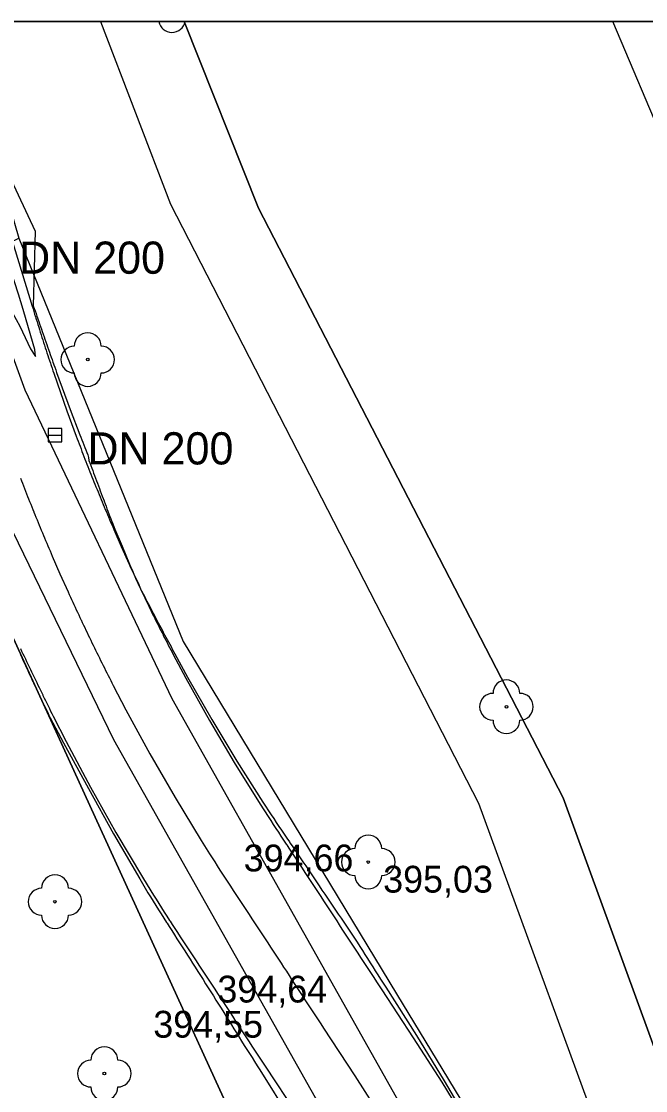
# Model space of a CAD drawing. Extents: x -574342 to -508101, y -1143544 to -1123894.
# Drawn here: x -508473.95 to -508450.68, y -1143155.94 to -1143116.06 of the extents above; entities that cross this region are included whole.
import ezdxf

# ---------------------------------------------------------------- set-up
doc = ezdxf.new("R2010")
doc.units = 0
for name, color, linetype in [('01_PARCELY_NAVRH_PC', 7, 'Continuous'), ('01_PARCELY_NAVRH_ŽP', 7, 'Continuous'), ('1000', 7, 'Continuous'), ('15', 7, 'Continuous'), ('21', 7, 'Continuous'), ('37', 7, 'Continuous'), ('52', 7, 'Continuous'), ('54', 7, 'Continuous'), ('55', 7, 'Continuous'), ('Level 1', 7, 'Continuous'), ('Level 255', 7, 'Continuous'), ('VRST VEDL', 7, 'Continuous')]:
    doc.layers.add(name, color=color, linetype=linetype)

msp = doc.modelspace()

# ---------------------------------------------------------------- linework, layer by layer
at = {"layer": '01_PARCELY_NAVRH_PC'}
msp.add_lwpolyline([(-508445.99, -1143206.42), (-508454.33, -1143183.49), (-508456.87, -1143173.84), (-508463.3, -1143163.03), (-508476.26, -1143134.7), (-508479.46, -1143126.74), (-508474.05, -1143124.14), (-508467.92, -1143139.18), (-508459.97, -1143152.33), (-508456.09, -1143158.71), (-508451.57, -1143168.14), (-508437.66, -1143207.58)], dxfattribs=at)
at = {"layer": '01_PARCELY_NAVRH_ŽP'}
for p, q in [((-508467.879, -1143116.058), (-508476.398, -1143116.058)), ((-508437, -1143116.058), (-508467.879, -1143116.058))]:
    msp.add_line(p, q, dxfattribs=at)
for points in [[(-508476.398, -1143116.058), (-508474.05, -1143124.14), (-508467.92, -1143139.18), (-508459.97, -1143152.33), (-508456.09, -1143158.71), (-508451.57, -1143168.14), (-508437.66, -1143207.58), (-508425.52, -1143241.92), (-508422.7, -1143249.88), (-508420.04, -1143252.1), (-508417.38, -1143252.95), (-508415.56, -1143252.78), (-508448.24, -1143160.16), (-508453.75, -1143145.01), (-508465.11, -1143123.03), (-508467.879, -1143116.058)], [(-508467.879, -1143116.058), (-508465.11, -1143123.03), (-508453.75, -1143145.01), (-508448.24, -1143160.16), (-508415.56, -1143252.78), (-508437, -1143116.058)]]:
    msp.add_lwpolyline(points, dxfattribs=at)
msp.add_lwpolyline([(-508521.06, -1143176.58), (-508518.2, -1143171.1), (-508515.68, -1143172.08), (-508512.27, -1143171.56), (-508509.12, -1143169.33), (-508497.89, -1143158.09), (-508486.83, -1143153.3), (-508481.34, -1143149.03), (-508479.12, -1143143.52), (-508479.68, -1143136.88), (-508476.26, -1143134.7), (-508463.3, -1143163.03), (-508471.45, -1143157.79), (-508480.5, -1143156.13), (-508491.25, -1143159.19), (-508499.36, -1143164.43), (-508507.52, -1143173.92), (-508509.38, -1143179.27), (-508513.26, -1143177.6)], close=True, dxfattribs=at)
at = {"layer": '1000'}
for points in [[(-508476.731, -1143116.058), (-508476.722, -1143116.092), (-508476.694, -1143116.192), (-508476.667, -1143116.292), (-508476.64, -1143116.392), (-508476.613, -1143116.492), (-508476.585, -1143116.592), (-508476.558, -1143116.691), (-508476.53, -1143116.791), (-508476.502, -1143116.891), (-508476.475, -1143116.991), (-508476.447, -1143117.091), (-508476.419, -1143117.19), (-508476.391, -1143117.29), (-508476.362, -1143117.39), (-508476.334, -1143117.489), (-508476.306, -1143117.589), (-508476.277, -1143117.689), (-508476.249, -1143117.788), (-508476.22, -1143117.888), (-508476.192, -1143117.987), (-508476.163, -1143118.087), (-508473.44, -1143123.887)], [(-508473.44, -1143123.887), (-508473.509, -1143126.661), (-508473.475, -1143126.76), (-508473.441, -1143126.858), (-508473.407, -1143126.956), (-508473.373, -1143127.055), (-508473.354, -1143127.11), (-508473.339, -1143127.152), (-508473.306, -1143127.247), (-508473.273, -1143127.342), (-508473.24, -1143127.437), (-508473.207, -1143127.532), (-508473.174, -1143127.628), (-508473.141, -1143127.723), (-508473.108, -1143127.818), (-508473.075, -1143127.913), (-508473.042, -1143128.008), (-508473.009, -1143128.103), (-508472.976, -1143128.198), (-508472.943, -1143128.293), (-508472.909, -1143128.389), (-508472.876, -1143128.484), (-508472.842, -1143128.578), (-508472.808, -1143128.673), (-508472.774, -1143128.768), (-508472.753, -1143128.827), (-508472.74, -1143128.863), (-508472.706, -1143128.958), (-508472.672, -1143129.052), (-508472.638, -1143129.147), (-508472.129, -1143130.534), (-508471.77, -1143131.474), (-508471.733, -1143131.569), (-508471.696, -1143131.663), (-508471.659, -1143131.757), (-508471.622, -1143131.852), (-508471.585, -1143131.946), (-508471.547, -1143132.04), (-508471.509, -1143132.134), (-508471.473, -1143132.227), (-508471.472, -1143132.228), (-508471.445, -1143132.326), (-508471.432, -1143132.429), (-508471.399, -1143132.525), (-508471.364, -1143132.621), (-508471.329, -1143132.716), (-508471.294, -1143132.811), (-508471.258, -1143132.906), (-508471.222, -1143133), (-508471.186, -1143133.095), (-508471.15, -1143133.19), (-508471.115, -1143133.285), (-508471.08, -1143133.379), (-508471.08, -1143133.38), (-508471.045, -1143133.475), (-508471.01, -1143133.571), (-508470.975, -1143133.666), (-508470.94, -1143133.761), (-508470.905, -1143133.856), (-508470.872, -1143133.944), (-508470.869, -1143133.951), (-508470.834, -1143134.046), (-508470.798, -1143134.141), (-508470.761, -1143134.235), (-508470.725, -1143134.33), (-508470.688, -1143134.425), (-508470.651, -1143134.519), (-508470.614, -1143134.613), (-508470.577, -1143134.708), (-508470.539, -1143134.802), (-508470.502, -1143134.896), (-508470.464, -1143134.99), (-508470.199, -1143135.634), (-508469.92, -1143136.297), (-508469.88, -1143136.391), (-508469.841, -1143136.484), (-508469.801, -1143136.577), (-508469.761, -1143136.671), (-508469.721, -1143136.764), (-508469.598, -1143136.998), (-508469.508, -1143137.224), (-508469.469, -1143137.301), (-508469.462, -1143137.314), (-508469.415, -1143137.404), (-508469.369, -1143137.495), (-508469.322, -1143137.585), (-508469.275, -1143137.675), (-508469.228, -1143137.765), (-508469.182, -1143137.855), (-508469.135, -1143137.945), (-508469.088, -1143138.035), (-508469.041, -1143138.125), (-508468.995, -1143138.215), (-508468.948, -1143138.305), (-508468.901, -1143138.394), (-508468.901, -1143138.395), (-508468.853, -1143138.484), (-508468.805, -1143138.573), (-508468.758, -1143138.663), (-508468.71, -1143138.752), (-508468.662, -1143138.842), (-508468.624, -1143138.913), (-508468.614, -1143138.931), (-508468.566, -1143139.02), (-508468.518, -1143139.11), (-508468.47, -1143139.199), (-508468.422, -1143139.288), (-508468.374, -1143139.378), (-508468.326, -1143139.467), (-508468.278, -1143139.556), (-508468.23, -1143139.645), (-508467.757, -1143140.512), (-508466.856, -1143142.09), (-508465.92, -1143143.646), (-508464.948, -1143145.18), (-508464.643, -1143145.647), (-508464.547, -1143145.792), (-508464.45, -1143145.937), (-508464.353, -1143146.082), (-508464.255, -1143146.227), (-508464.157, -1143146.371), (-508464.059, -1143146.516), (-508463.96, -1143146.66), (-508463.94, -1143146.689), (-508463.94, -1143146.689), (-508463.86, -1143146.808), (-508463.759, -1143146.958), (-508463.658, -1143147.108), (-508463.556, -1143147.257), (-508463.455, -1143147.407), (-508463.354, -1143147.556), (-508463.252, -1143147.706), (-508463.151, -1143147.855), (-508463.049, -1143148.005), (-508462.948, -1143148.154), (-508462.847, -1143148.304), (-508462.746, -1143148.454), (-508462.645, -1143148.603), (-508462.543, -1143148.753), (-508462.442, -1143148.902), (-508462.34, -1143149.052), (-508462.239, -1143149.201), (-508462.137, -1143149.35), (-508462.035, -1143149.5), (-508461.933, -1143149.649), (-508461.834, -1143149.8), (-508461.734, -1143149.951), (-508461.635, -1143150.101), (-508461.536, -1143150.252), (-508461.436, -1143150.403), (-508461.339, -1143150.555), (-508461.242, -1143150.708), (-508461.146, -1143150.861), (-508461.049, -1143151.013), (-508460.952, -1143151.166), (-508460.855, -1143151.318), (-508460.758, -1143151.47), (-508460.661, -1143151.623), (-508460.564, -1143151.775), (-508460.467, -1143151.928), (-508460.371, -1143152.08), (-508459.228, -1143153.886), (-508458.193, -1143155.565), (-508457.198, -1143157.266)], [(-508474.325, -1143124.158), (-508473.55, -1143126.674), (-508473.519, -1143126.773), (-508473.488, -1143126.873), (-508473.458, -1143126.972), (-508473.427, -1143127.071), (-508473.41, -1143127.128), (-508473.397, -1143127.169), (-508473.367, -1143127.266), (-508473.337, -1143127.362), (-508473.307, -1143127.458), (-508473.277, -1143127.554), (-508473.247, -1143127.651), (-508473.216, -1143127.747), (-508473.186, -1143127.843), (-508473.155, -1143127.939), (-508473.124, -1143128.035), (-508473.093, -1143128.131), (-508473.062, -1143128.227), (-508473.031, -1143128.322), (-508473, -1143128.418), (-508472.968, -1143128.514), (-508472.937, -1143128.61), (-508472.905, -1143128.705), (-508472.873, -1143128.801), (-508472.854, -1143128.86), (-508472.842, -1143128.897), (-508472.81, -1143128.992), (-508472.777, -1143129.088), (-508472.745, -1143129.183), (-508472.257, -1143130.58), (-508471.909, -1143131.527), (-508471.873, -1143131.622), (-508471.837, -1143131.717), (-508471.801, -1143131.811), (-508471.765, -1143131.906), (-508471.729, -1143132.001), (-508471.693, -1143132.096), (-508471.656, -1143132.19), (-508471.62, -1143132.284), (-508471.62, -1143132.285), (-508471.583, -1143132.38), (-508471.546, -1143132.474), (-508471.509, -1143132.569), (-508471.472, -1143132.663), (-508471.435, -1143132.758), (-508471.398, -1143132.852), (-508471.361, -1143132.946), (-508471.323, -1143133.041), (-508471.285, -1143133.135), (-508471.247, -1143133.229), (-508471.21, -1143133.323), (-508471.172, -1143133.416), (-508471.172, -1143133.417), (-508471.133, -1143133.511), (-508471.095, -1143133.605), (-508471.057, -1143133.699), (-508471.018, -1143133.793), (-508470.979, -1143133.887), (-508470.943, -1143133.974), (-508470.941, -1143133.98), (-508470.902, -1143134.074), (-508470.863, -1143134.168), (-508470.824, -1143134.261), (-508470.784, -1143134.355), (-508470.745, -1143134.449), (-508470.705, -1143134.542), (-508470.666, -1143134.635), (-508470.626, -1143134.729), (-508470.586, -1143134.822), (-508470.546, -1143134.915), (-508470.506, -1143135.008), (-508470.227, -1143135.647), (-508469.933, -1143136.303), (-508469.891, -1143136.396), (-508469.849, -1143136.488), (-508469.807, -1143136.58), (-508469.765, -1143136.672), (-508469.723, -1143136.765), (-508469.68, -1143136.857), (-508469.637, -1143136.949), (-508469.595, -1143137.041), (-508469.552, -1143137.133), (-508469.509, -1143137.224), (-508469.472, -1143137.303), (-508469.466, -1143137.316), (-508469.422, -1143137.408), (-508469.379, -1143137.5), (-508469.335, -1143137.591), (-508469.292, -1143137.683), (-508469.248, -1143137.774), (-508469.204, -1143137.866), (-508469.16, -1143137.957), (-508469.116, -1143138.048), (-508469.072, -1143138.14), (-508469.028, -1143138.231), (-508468.983, -1143138.322), (-508468.939, -1143138.412), (-508468.939, -1143138.413), (-508468.893, -1143138.504), (-508468.847, -1143138.594), (-508468.802, -1143138.685), (-508468.756, -1143138.775), (-508468.709, -1143138.865), (-508468.673, -1143138.937), (-508468.663, -1143138.956), (-508468.617, -1143139.046), (-508468.57, -1143139.136), (-508468.524, -1143139.226), (-508468.477, -1143139.316), (-508468.43, -1143139.406), (-508468.384, -1143139.496), (-508468.337, -1143139.586), (-508468.289, -1143139.676), (-508467.824, -1143140.547), (-508466.938, -1143142.136), (-508466.015, -1143143.703), (-508465.056, -1143145.247), (-508464.754, -1143145.717), (-508464.659, -1143145.864), (-508464.563, -1143146.01), (-508464.468, -1143146.156), (-508464.371, -1143146.302), (-508464.275, -1143146.448), (-508464.178, -1143146.593), (-508464.081, -1143146.739), (-508464.061, -1143146.768), (-508464.061, -1143146.769), (-508463.982, -1143146.888), (-508463.883, -1143147.039), (-508463.784, -1143147.191), (-508463.685, -1143147.342), (-508463.586, -1143147.493), (-508463.487, -1143147.644), (-508463.388, -1143147.795), (-508463.289, -1143147.946), (-508463.19, -1143148.097), (-508463.09, -1143148.248), (-508462.991, -1143148.399), (-508462.892, -1143148.55), (-508462.793, -1143148.701), (-508462.694, -1143148.852), (-508462.595, -1143149.003), (-508462.496, -1143149.154), (-508462.397, -1143149.305), (-508462.298, -1143149.456), (-508462.199, -1143149.607), (-508462.1, -1143149.758), (-508462.001, -1143149.909), (-508461.901, -1143150.06), (-508461.802, -1143150.211), (-508461.703, -1143150.362), (-508461.604, -1143150.513), (-508461.505, -1143150.664), (-508461.406, -1143150.815), (-508461.307, -1143150.966), (-508461.208, -1143151.117), (-508461.109, -1143151.268), (-508461.01, -1143151.419), (-508460.911, -1143151.57), (-508460.812, -1143151.722), (-508460.712, -1143151.873), (-508460.613, -1143152.024), (-508460.514, -1143152.175), (-508459.342, -1143153.961), (-508458.282, -1143155.62), (-508457.262, -1143157.304)], [(-508473.99, -1143139.445), (-508473.944, -1143139.543), (-508473.897, -1143139.641), (-508473.851, -1143139.738), (-508473.805, -1143139.836), (-508473.758, -1143139.933), (-508473.711, -1143140.03), (-508473.665, -1143140.128), (-508473.618, -1143140.225), (-508473.571, -1143140.322), (-508473.523, -1143140.419), (-508473.476, -1143140.516), (-508473.429, -1143140.612), (-508473.429, -1143140.613), (-508473.382, -1143140.71), (-508473.335, -1143140.808), (-508473.288, -1143140.905), (-508473.241, -1143141.002), (-508473.194, -1143141.099), (-508473.157, -1143141.177), (-508473.147, -1143141.196), (-508473.1, -1143141.293), (-508473.052, -1143141.39), (-508473.005, -1143141.487), (-508472.957, -1143141.584), (-508472.909, -1143141.681), (-508472.861, -1143141.778), (-508472.813, -1143141.874), (-508472.764, -1143141.971), (-508472.287, -1143142.909), (-508471.377, -1143144.62), (-508470.427, -1143146.31), (-508469.437, -1143147.977), (-508469.126, -1143148.484), (-508469.027, -1143148.643), (-508468.929, -1143148.801), (-508468.83, -1143148.959), (-508468.73, -1143149.117), (-508468.63, -1143149.274), (-508468.53, -1143149.431), (-508468.43, -1143149.589), (-508468.409, -1143149.621), (-508468.409, -1143149.621), (-508468.33, -1143149.741), (-508468.231, -1143149.892), (-508468.132, -1143150.043), (-508468.033, -1143150.194), (-508467.934, -1143150.345), (-508467.835, -1143150.496), (-508467.736, -1143150.647), (-508467.637, -1143150.798), (-508467.537, -1143150.949), (-508467.438, -1143151.1), (-508467.339, -1143151.251), (-508467.24, -1143151.402), (-508467.141, -1143151.553), (-508467.042, -1143151.704), (-508466.943, -1143151.855), (-508466.844, -1143152.006), (-508466.745, -1143152.157), (-508466.646, -1143152.308), (-508466.547, -1143152.459), (-508466.448, -1143152.61), (-508466.348, -1143152.761), (-508466.249, -1143152.913), (-508466.15, -1143153.064), (-508466.051, -1143153.215), (-508465.952, -1143153.366), (-508465.853, -1143153.517), (-508465.754, -1143153.668), (-508465.655, -1143153.819), (-508465.556, -1143153.97), (-508465.457, -1143154.121), (-508465.358, -1143154.272), (-508465.259, -1143154.423), (-508465.159, -1143154.574), (-508465.06, -1143154.725), (-508464.961, -1143154.876), (-508464.862, -1143155.027), (-508463.69, -1143156.813)], [(-508473.985, -1143139.682), (-508473.94, -1143139.78), (-508473.894, -1143139.878), (-508473.849, -1143139.976), (-508473.804, -1143140.075), (-508473.759, -1143140.173), (-508473.714, -1143140.272), (-508473.669, -1143140.37), (-508473.623, -1143140.468), (-508473.577, -1143140.566), (-508473.532, -1143140.663), (-508473.531, -1143140.663), (-508473.486, -1143140.762), (-508473.44, -1143140.86), (-508473.395, -1143140.958), (-508473.349, -1143141.055), (-508473.302, -1143141.153), (-508473.265, -1143141.231), (-508473.256, -1143141.251), (-508473.209, -1143141.348), (-508473.162, -1143141.446), (-508473.115, -1143141.543), (-508473.067, -1143141.64), (-508473.02, -1143141.737), (-508472.972, -1143141.834), (-508472.924, -1143141.931), (-508472.875, -1143142.028), (-508472.385, -1143142.961), (-508471.455, -1143144.663), (-508470.519, -1143146.364), (-508469.543, -1143148.043), (-508469.235, -1143148.553), (-508469.137, -1143148.712), (-508469.039, -1143148.871), (-508468.94, -1143149.03), (-508468.841, -1143149.188), (-508468.742, -1143149.347), (-508468.643, -1143149.505), (-508468.543, -1143149.663), (-508468.523, -1143149.695), (-508468.522, -1143149.696), (-508468.445, -1143149.816), (-508468.347, -1143149.968), (-508468.249, -1143150.12), (-508468.152, -1143150.272), (-508468.054, -1143150.424), (-508467.957, -1143150.576), (-508467.859, -1143150.728), (-508467.762, -1143150.88), (-508467.665, -1143151.033), (-508467.568, -1143151.185), (-508467.471, -1143151.337), (-508467.374, -1143151.49), (-508467.277, -1143151.642), (-508467.18, -1143151.795), (-508467.084, -1143151.948), (-508466.987, -1143152.1), (-508466.891, -1143152.253), (-508466.795, -1143152.406), (-508466.699, -1143152.559), (-508466.603, -1143152.712), (-508466.507, -1143152.865), (-508466.411, -1143153.019), (-508466.316, -1143153.172), (-508466.22, -1143153.325), (-508466.125, -1143153.479), (-508466.029, -1143153.632), (-508465.934, -1143153.786), (-508465.839, -1143153.939), (-508465.744, -1143154.093), (-508465.649, -1143154.247), (-508465.548, -1143154.397), (-508465.447, -1143154.547), (-508465.351, -1143154.7), (-508465.256, -1143154.853), (-508465.16, -1143155.007), (-508465.065, -1143155.16), (-508463.936, -1143156.975)]]:
    msp.add_lwpolyline(points, dxfattribs=at)
at = {"layer": '21'}
msp.add_lwpolyline([(-508473.989, -1143133.09), (-508473.952, -1143133.187), (-508473.951, -1143133.187), (-508473.914, -1143133.285), (-508473.876, -1143133.383), (-508473.837, -1143133.48), (-508473.799, -1143133.578), (-508473.761, -1143133.675), (-508473.722, -1143133.773), (-508473.684, -1143133.87), (-508473.645, -1143133.967), (-508473.606, -1143134.065), (-508473.567, -1143134.162), (-508473.528, -1143134.259), (-508473.489, -1143134.355), (-508473.489, -1143134.356), (-508473.449, -1143134.453), (-508473.41, -1143134.55), (-508473.37, -1143134.647), (-508473.33, -1143134.744), (-508473.29, -1143134.841), (-508473.253, -1143134.931), (-508473.25, -1143134.938), (-508473.21, -1143135.034), (-508473.17, -1143135.131), (-508473.129, -1143135.228), (-508473.089, -1143135.324), (-508473.048, -1143135.421), (-508473.007, -1143135.517), (-508472.966, -1143135.614), (-508472.925, -1143135.71), (-508472.884, -1143135.806), (-508472.843, -1143135.902), (-508472.802, -1143135.999), (-508472.514, -1143136.658), (-508472.21, -1143137.335), (-508472.167, -1143137.431), (-508472.124, -1143137.526), (-508472.08, -1143137.621), (-508472.037, -1143137.716), (-508471.993, -1143137.811), (-508471.949, -1143137.906), (-508471.905, -1143138.001), (-508471.861, -1143138.096), (-508471.816, -1143138.191), (-508471.772, -1143138.286), (-508471.734, -1143138.367), (-508471.728, -1143138.381), (-508471.683, -1143138.475), (-508471.638, -1143138.57), (-508471.593, -1143138.665), (-508471.548, -1143138.759), (-508471.503, -1143138.854), (-508471.458, -1143138.948), (-508471.412, -1143139.042), (-508471.367, -1143139.137), (-508471.321, -1143139.231), (-508471.276, -1143139.325), (-508471.23, -1143139.419), (-508471.184, -1143139.512), (-508471.184, -1143139.513), (-508471.138, -1143139.607), (-508471.091, -1143139.701), (-508471.045, -1143139.795), (-508470.999, -1143139.889), (-508470.952, -1143139.982), (-508470.915, -1143140.057), (-508470.905, -1143140.076), (-508470.858, -1143140.17), (-508470.811, -1143140.263), (-508470.764, -1143140.357), (-508470.717, -1143140.45), (-508470.67, -1143140.543), (-508470.622, -1143140.637), (-508470.575, -1143140.73), (-508470.527, -1143140.823), (-508470.056, -1143141.728), (-508469.158, -1143143.378), (-508468.221, -1143145.006), (-508467.247, -1143146.612), (-508466.94, -1143147.101), (-508466.843, -1143147.253), (-508466.746, -1143147.405), (-508466.649, -1143147.557), (-508466.551, -1143147.709), (-508466.453, -1143147.861), (-508466.354, -1143148.012), (-508466.255, -1143148.164), (-508466.235, -1143148.194), (-508466.235, -1143148.195), (-508466.156, -1143148.315), (-508466.057, -1143148.466), (-508465.958, -1143148.617), (-508465.859, -1143148.768), (-508465.76, -1143148.919), (-508465.661, -1143149.07), (-508465.562, -1143149.221), (-508465.463, -1143149.372), (-508465.364, -1143149.523), (-508465.264, -1143149.674), (-508465.165, -1143149.825), (-508465.066, -1143149.976), (-508464.967, -1143150.127), (-508464.868, -1143150.278), (-508464.769, -1143150.429), (-508464.67, -1143150.58), (-508464.571, -1143150.731), (-508464.472, -1143150.882), (-508464.373, -1143151.033), (-508464.274, -1143151.184), (-508464.175, -1143151.335), (-508464.075, -1143151.486), (-508463.976, -1143151.637), (-508463.877, -1143151.788), (-508463.778, -1143151.939), (-508463.679, -1143152.09), (-508463.58, -1143152.242), (-508463.481, -1143152.393), (-508463.382, -1143152.544), (-508463.283, -1143152.695), (-508463.184, -1143152.846), (-508463.085, -1143152.997), (-508462.986, -1143153.148), (-508462.886, -1143153.299), (-508462.787, -1143153.45), (-508462.688, -1143153.601), (-508461.516, -1143155.387), (-508460.489, -1143156.994)], dxfattribs=at)
at = {"layer": '37'}
for points in [[(-508470.5, -1143142.85), (-508477.03, -1143129.41), (-508478.76, -1143124.67), (-508476.03, -1143123.74), (-508473.82, -1143129.8)], [(-508470.5, -1143142.85), (-508477.03, -1143129.41), (-508478.76, -1143124.67), (-508476.03, -1143123.74), (-508473.82, -1143129.8)], [(-508473.82, -1143129.8), (-508468.34, -1143141.31), (-508458.53, -1143158.76), (-508453.13, -1143170.86), (-508439.96, -1143210.5), (-508427.56, -1143241.73), (-508421.57, -1143265.72), (-508416.35, -1143292.6), (-508412.42, -1143304.7), (-508408.82, -1143311.83)], [(-508473.82, -1143129.8), (-508468.34, -1143141.31), (-508458.53, -1143158.76), (-508453.13, -1143170.86), (-508439.96, -1143210.5), (-508427.56, -1143241.73), (-508421.57, -1143265.72), (-508416.35, -1143292.6), (-508412.42, -1143304.7), (-508408.82, -1143311.83)], [(-508408.82, -1143311.83), (-508404.37, -1143317.04), (-508398.21, -1143321.18), (-508393.66, -1143322.44), (-508393.79, -1143324.58), (-508400.56, -1143323.11), (-508406.32, -1143319.06), (-508411.41, -1143313.16), (-508415.31, -1143305.9), (-508419.33, -1143292.88), (-508424.96, -1143264.72), (-508428.49, -1143248.11), (-508430.27, -1143242.09), (-508442.28, -1143211.48), (-508455.59, -1143171.17), (-508460.82, -1143160.05), (-508470.5, -1143142.85)], [(-508408.82, -1143311.83), (-508404.37, -1143317.04), (-508398.21, -1143321.18), (-508393.66, -1143322.44), (-508393.79, -1143324.58), (-508400.56, -1143323.11), (-508406.32, -1143319.06), (-508411.41, -1143313.16), (-508415.31, -1143305.9), (-508419.33, -1143292.88), (-508424.96, -1143264.72), (-508428.49, -1143248.11), (-508430.27, -1143242.09), (-508442.28, -1143211.48), (-508455.59, -1143171.17), (-508460.82, -1143160.05), (-508470.5, -1143142.85)]]:
    msp.add_lwpolyline(points, dxfattribs=at)
at = {"layer": '52'}
msp.add_line((-508472.95, -1143131.49), (-508472.45, -1143131.49), dxfattribs=at)
msp.add_lwpolyline([(-508472.95, -1143131.74), (-508472.45, -1143131.74), (-508472.45, -1143131.24), (-508472.95, -1143131.24)], close=True, dxfattribs=at)
at = {"layer": '54'}
for centre in [(-508471.48, -1143128.67), (-508455.87, -1143141.62), (-508461.02, -1143147.41), (-508472.7, -1143148.89), (-508470.86, -1143155.3)]:
    msp.add_circle(centre, 0.05, dxfattribs=at)
for centre, start, end in [((-508468.34, -1143115.97), 190.1163, 349.8837), ((-508471.48, -1143128.17), 0, 180), ((-508471.98, -1143128.67), 90, 270), ((-508470.98, -1143128.67), 270, 90), ((-508471.48, -1143129.17), 180, 0), ((-508455.87, -1143141.12), 0, 180), ((-508456.37, -1143141.62), 90, 270), ((-508455.37, -1143141.62), 270, 90), ((-508455.87, -1143142.12), 180, 0), ((-508461.02, -1143146.91), 0, 180), ((-508461.52, -1143147.41), 90, 270), ((-508460.52, -1143147.41), 270, 90), ((-508472.7, -1143148.39), 0, 180), ((-508461.02, -1143147.91), 180, 0), ((-508473.2, -1143148.89), 90, 270), ((-508472.2, -1143148.89), 270, 90), ((-508472.7, -1143149.39), 180, 0), ((-508470.86, -1143154.8), 0, 180), ((-508471.36, -1143155.3), 90, 270), ((-508470.36, -1143155.3), 270, 90), ((-508470.86, -1143155.8), 180, 0)]:
    msp.add_arc(centre, 0.5, start, end, dxfattribs=at)
at = {"layer": '55'}
msp.add_lwpolyline([(-508471.007, -1143116.058), (-508468.39, -1143122.87), (-508456.91, -1143145.22), (-508451.68, -1143159.54), (-508438.58, -1143205.02)], dxfattribs=at)
msp.add_lwpolyline([(-508471.007, -1143116.058), (-508468.39, -1143122.87), (-508456.91, -1143145.22), (-508451.68, -1143159.54), (-508438.58, -1143205.02)], dxfattribs=at)
at = {"layer": 'Level 1'}
msp.add_lwpolyline([(-508703.096, -1143116.058), (-508109.096, -1143116.058), (-508109.096, -1143536.058), (-508703.096, -1143536.058)], close=True, dxfattribs=at)
at = {"layer": 'VRST VEDL'}
msp.add_lwpolyline([(-508445.897, -1143130.235), (-508451.91, -1143116.058)], dxfattribs=at)
msp.add_lwpolyline([(-508474.345, -1143125.352), (-508474.6, -1143125.179), (-508474.703, -1143125.119), (-508474.781, -1143125.087), (-508474.835, -1143125.081), (-508474.896, -1143125.144), (-508474.963, -1143125.274), (-508475.036, -1143125.472), (-508475.017, -1143125.756), (-508474.904, -1143126.127), (-508474.699, -1143126.583), (-508474.551, -1143126.838), (-508474.463, -1143126.891), (-508474.433, -1143126.743), (-508474.28, -1143126.923), (-508474.006, -1143127.431), (-508473.609, -1143128.267), (-508473.424, -1143128.555), (-508473.449, -1143128.295), (-508473.686, -1143127.486), (-508473.891, -1143126.799), (-508474.064, -1143126.235)], close=True, dxfattribs=at)

# ---------------------------------------------------------------- texts
at = {"layer": '15'}
for p in [(-508474.038, -1143125.47), (-508474.038, -1143125.47), (-508471.489, -1143132.582), (-508471.489, -1143132.582)]:
    msp.add_text('DN 200', height=1.2, dxfattribs=at).set_placement(p)
at = {"layer": 'Level 255'}
for s, p in [('394,66', (-508465.665, -1143147.76)), ('395,03', (-508460.465, -1143148.55)), ('394,64', (-508466.645, -1143152.65)), ('394,55', (-508469.035, -1143153.96))]:
    msp.add_text(s, height=1, dxfattribs=at).set_placement(p)

doc.saveas('drawing.dxf')
